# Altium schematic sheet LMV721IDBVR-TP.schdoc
size 127 x 101 mm
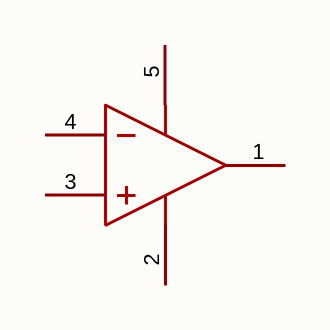
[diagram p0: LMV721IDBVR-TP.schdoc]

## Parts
U?  lmv721idbvr-tp  [SOT-23-5_L2.9-W1.6-P0.95-LS2.8-BR]  (value not drawn)

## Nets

Not connected (* = marked no-connect by the designer): U? 1(VOUT) 2(V-) 3(IN+) 4(IN-) 5(V+)

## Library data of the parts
U? = lmv721idbvr-tp: 放大器数:2;轨到轨:轨到轨输入,轨到轨输出;增益带宽积(GBW):10MHz;输入失调电压(Vos):5mV;压摆率(SR):4.5V/us;输入偏置电流(Ib):100pA;; Manufacturer: TECH PUBLIC(台舟); AddInBom: yes; ModelId: 7ba65df16e7b4570af156e925f9c37fe; ModelTransform: 114.173,114.173,0,90,0,0,0,0,0; Number of Channels: 2; Maximum Power Supply Range (Vdd-Vss): 5.5V; Gain Bandwidth Product: 10MHz; Vos - Input Offset Voltage: 5mV; Input Offset Voltage Drift(Vos TC): 300nV/℃; Ib - Input Bias Current: 100pA; Input Voltage Noise Density: 30nV/√Hz@1kHz; Common Mode Rejection Ratio(CMRR): 80dB; Quiescent Current: 800uA; Output Current: 50mA; Single supply: 2.2V~5.5V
